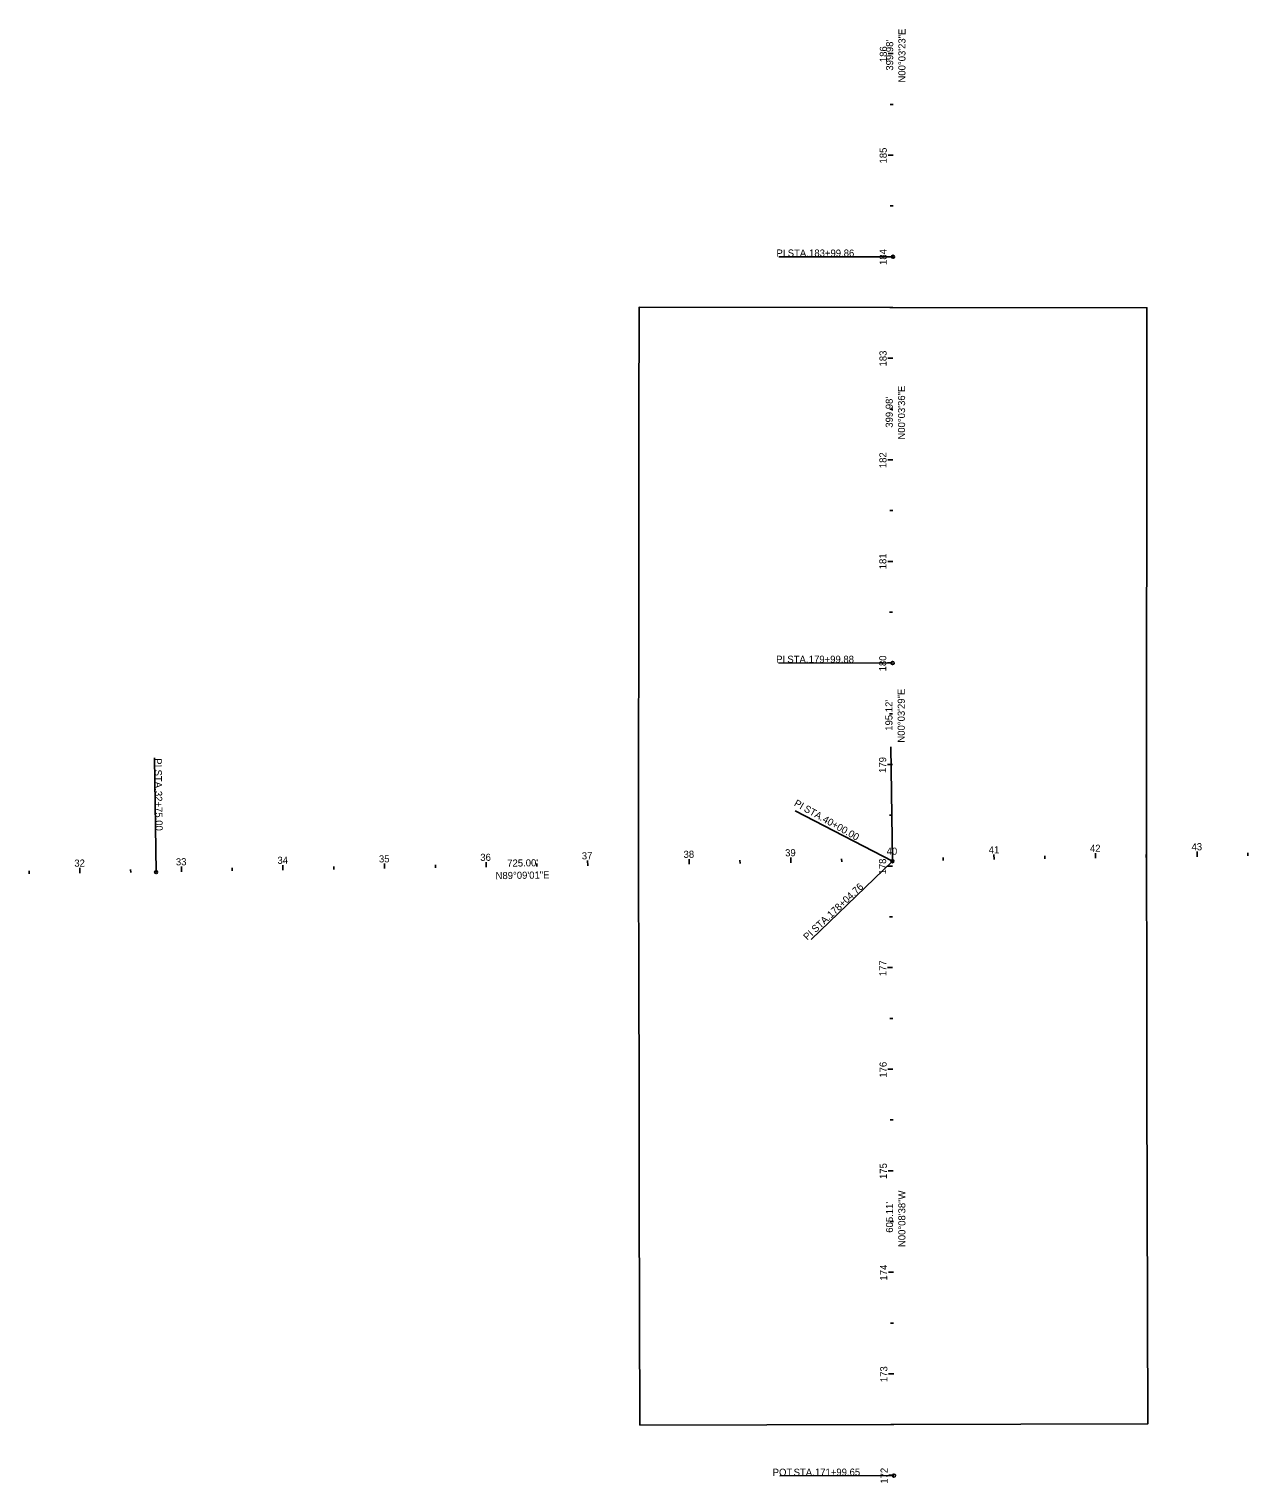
# Model space of a CAD drawing. Extents: x 1805326 to 1810276, y 297762 to 303660.
# Drawn here: x 1807814 to 1809014, y 297762 to 299193 of the extents above; entities that cross this region are included whole.
import ezdxf

# ---------------------------------------------------------------- set-up
doc = ezdxf.new("R2010")
doc.units = 0
for name, color, linetype in [('GE_P_Alignment_100_Bearings', 7, 'Continuous'), ('GE_P_Alignment_100_Cardinal_Points', 7, 'Continuous'), ('GE_P_Alignment_100_Distances', 7, 'Continuous'), ('GE_P_Alignment_100_Stations', 7, 'Continuous'), ('SH_Data', 7, 'Continuous'), ('SH_Named_Boundary', 7, 'Continuous')]:
    doc.layers.add(name, color=color, linetype=linetype)

msp = doc.modelspace()

# ---------------------------------------------------------------- linework, layer by layer
at = {"layer": 'GE_P_Alignment_100_Cardinal_Points'}
for p, q in [((1808664.7, 298969.1), (1808552.2, 298969.2)), ((1808664.3, 298569.1), (1808551.8, 298569.2)), ((1808664.1, 298374), (1808662.4, 298486.5)), ((1807939.2, 298363.2), (1807937.5, 298475.7)), ((1808665.6, 297768.9), (1808553.1, 297768.6))]:
    msp.add_line(p, q, dxfattribs=at)
for centre in [(1808664.7, 298969.1), (1808664.3, 298569.1), (1807939.2, 298363.2), (1808664.1, 298374), (1808665.6, 297768.9)]:
    msp.add_circle(centre, 1.5, dxfattribs=at)
at = {"layer": 'GE_P_Alignment_100_Stations'}
for p, q in [((1808664.9, 299169.2), (1808659.9, 299169.2)), ((1808664.8, 299119.2), (1808661.8, 299119.2)), ((1808664.8, 299069.2), (1808659.8, 299069.2)), ((1808664.7, 299019.2), (1808661.7, 299019.2)), ((1808664.7, 298969.2), (1808659.7, 298969.2)), ((1808664.6, 298919.2), (1808661.6, 298919.2)), ((1808664.6, 298869.2), (1808659.6, 298869.2)), ((1808664.5, 298819.2), (1808661.5, 298819.2)), ((1808664.5, 298769.2), (1808659.5, 298769.2)), ((1808664.4, 298719.2), (1808661.4, 298719.2)), ((1808664.4, 298669.2), (1808659.4, 298669.2)), ((1808664.3, 298619.2), (1808661.3, 298619.2)), ((1808664.3, 298569.2), (1808659.3, 298569.2)), ((1808664.2, 298519.2), (1808661.2, 298519.2)), ((1808664.2, 298469.2), (1808659.2, 298469.2)), ((1808664.1, 298419.2), (1808661.1, 298419.2)), ((1808664.1, 298374), (1808664, 298379)), ((1808764.1, 298375.5), (1808764, 298380.5)), ((1808814.1, 298376.2), (1808814, 298379.2)), ((1808864.1, 298377), (1808864, 298382)), ((1808914, 298377.7), (1808914, 298380.7)), ((1808964, 298378.4), (1808964, 298383.4)), ((1809014, 298379.2), (1809014, 298382.2)), ((1807814.2, 298361.6), (1807814.1, 298364.6)), ((1807864.2, 298362.3), (1807864.1, 298367.3)), ((1807914.2, 298362.9), (1807914.1, 298365.9)), ((1807964.2, 298363.6), (1807964.1, 298368.6)), ((1808014.1, 298364.3), (1808014.1, 298367.3)), ((1808064.1, 298365.1), (1808064.1, 298370.1)), ((1808114.1, 298365.8), (1808114.1, 298368.8)), ((1808164.1, 298366.6), (1808164.1, 298371.6)), ((1808214.1, 298367.3), (1808214.1, 298370.3)), ((1808264.1, 298368.1), (1808264, 298373.1)), ((1808314.1, 298368.8), (1808314.1, 298371.8)), ((1808364.1, 298369.5), (1808364, 298374.5)), ((1808414.1, 298370.3), (1808414.1, 298373.3)), ((1808464.1, 298371), (1808464, 298376)), ((1808514.1, 298371.8), (1808514, 298374.8)), ((1808564.1, 298372.5), (1808564, 298377.5)), ((1808614.1, 298373.2), (1808614, 298376.2)), ((1808664.1, 298369.2), (1808659.1, 298369.2)), ((1808714.1, 298374.7), (1808714, 298377.7)), ((1808664.2, 298319.2), (1808661.2, 298319.2)), ((1808664.3, 298269.2), (1808659.3, 298269.2)), ((1808664.5, 298219.2), (1808661.5, 298219.2)), ((1808664.6, 298169.2), (1808659.6, 298169.2)), ((1808664.7, 298119.2), (1808661.7, 298119.2)), ((1808664.8, 298069.2), (1808659.8, 298069.2)), ((1808665, 298019.2), (1808662, 298019.2)), ((1808665.1, 297969.2), (1808660.1, 297969.2)), ((1808665.2, 297919.2), (1808662.2, 297919.2)), ((1808665.3, 297869.2), (1808660.3, 297869.2)), ((1808665.5, 297819.2), (1808662.5, 297819.2)), ((1808665.6, 297769.2), (1808660.6, 297769.2))]:
    msp.add_line(p, q, dxfattribs=at)
at = {"layer": 'SH_Data'}
for q in [(1808568.4, 298423.6), (1808584.1, 298296.7)]:
    msp.add_line((1808664.1, 298374), q, dxfattribs=at)
at = {"layer": 'SH_Named_Boundary'}
msp.add_lwpolyline([(1808415.5, 297818.6), (1808915.5, 297819.9), (1808915.2, 297929.9), (1808914.9, 298039.9), (1808914.6, 298149.9), (1808914.4, 298259.9), (1808914.1, 298369.9), (1808914.2, 298479), (1808914.3, 298589), (1808914.4, 298699), (1808914.5, 298809), (1808914.6, 298919), (1808414.6, 298919.5), (1808414.5, 298809.5), (1808414.4, 298699.5), (1808414.3, 298589.5), (1808414.2, 298479.5), (1808414.1, 298368.6), (1808414.4, 298258.6), (1808414.6, 298148.6), (1808414.9, 298038.6), (1808415.2, 297928.6)], close=True, dxfattribs=at)

# ---------------------------------------------------------------- texts
at = {"layer": 'GE_P_Alignment_100_Bearings'}
for s, rotation, p in [('N00°03\'23"E', 89.9436, (1808676.9, 299140.7)), ('N00°03\'36"E', 89.94, (1808676.5, 298789.1)), ('N00°03\'29"E', 89.9419, (1808676.2, 298490.7)), ('N89°09\'01"E', 0.8497, (1808273.4, 298356.2)), ('N00°08\'38"W', 90.1438, (1808676.9, 297994))]:
    msp.add_text(s, height=7, rotation=rotation, dxfattribs=at).set_placement(p)
at = {"layer": 'GE_P_Alignment_100_Cardinal_Points'}
for s, rotation, p in [('PI', 359.9436, (1808549.9, 298969.3)), (' STA. ', 359.9436, (1808558.4, 298969.3)), ('183+99.86', 359.9436, (1808582, 298969.3)), ('PI', 359.94, (1808549.6, 298569.3)), (' STA. ', 359.94, (1808558, 298569.3)), ('179+99.88', 359.94, (1808581.7, 298569.3)), ('PI', 270.8497, (1807937.6, 298475.2)), (' STA. ', 270.8497, (1807937.7, 298466.7)), ('32+75.00', 270.8497, (1807938.1, 298443.1)), ('PI', 330.6318, (1808566.6, 298429)), (' STA. ', 330.6318, (1808574, 298424.8)), ('40+00.00', 330.6318, (1808594.6, 298413.2)), ('178+04.76', 43.1579, (1808603.7, 298317.5)), (' STA. ', 43.1579, (1808586.5, 298301.4)), ('PI', 43.1579, (1808580.3, 298295.6)), ('POT', 0.1438, (1808546.2, 297768.7)), (' STA. ', 0.1438, (1808564.2, 297768.7)), ('171+99.65', 0.1438, (1808587.8, 297768.8))]:
    msp.add_text(s, height=7, rotation=rotation, dxfattribs=at).set_placement(p)
at = {"layer": 'GE_P_Alignment_100_Distances'}
for s, rotation, p in [("399.98'", 89.9436, (1808664.8, 299152.4)), ("399.98'", 89.94, (1808664.4, 298800.8)), ("195.12'", 89.9419, (1808664.1, 298502.4)), ("725.00'", 0.8497, (1808284.9, 298368.5)), ("605.11'", 90.1438, (1808664.7, 298008.1))]:
    msp.add_text(s, height=7, rotation=rotation, dxfattribs=at).set_placement(p)
at = {"layer": 'GE_P_Alignment_100_Stations'}
for s, rotation, p in [('186', 89.9436, (1808658.6, 299160.8)), ('185', 89.9436, (1808658.5, 299061)), ('184', 89.9436, (1808658.4, 298961.1)), ('183', 89.94, (1808658.3, 298861.1)), ('182', 89.94, (1808658.2, 298761)), ('181', 89.94, (1808658.1, 298661.4)), ('180', 89.94, (1808658, 298560.9)), ('179', 89.9419, (1808657.9, 298460.9)), ('35', 0.8497, (1808158.6, 298372.7)), ('36', 0.8497, (1808258.4, 298374.2)), ('37', 0.8497, (1808358.3, 298375.7)), ('38', 0.8497, (1808458.5, 298377.2)), ('39', 0.8497, (1808558.5, 298378.7)), ('40', 0.8496, (1808658.4, 298380.2)), ('41', 0.8496, (1808758.9, 298381.6)), ('42', 0.8496, (1808858.6, 298383.1)), ('43', 0.8496, (1808958.6, 298384.6)), ('32', 0.7316, (1807858.7, 298368.5)), ('33', 0.8497, (1807958.7, 298369.8)), ('34', 0.8497, (1808058.7, 298371.3)), ('178', 90.1438, (1808657.9, 298360.9)), ('177', 90.1438, (1808658.1, 298260.7)), ('176', 90.1438, (1808658.4, 298160.8)), ('175', 90.1438, (1808658.6, 298061)), ('174', 90.1438, (1808658.9, 297961)), ('173', 90.1438, (1808659.1, 297861)), ('172', 90.1438, (1808659.4, 297761))]:
    msp.add_text(s, height=7, rotation=rotation, dxfattribs=at).set_placement(p)

doc.saveas('drawing.dxf')
